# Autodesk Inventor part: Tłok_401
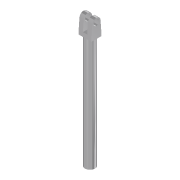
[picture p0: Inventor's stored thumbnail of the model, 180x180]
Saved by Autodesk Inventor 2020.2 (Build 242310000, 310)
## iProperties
Created: 2006-06
Part Number: Tłok_401
Document SubType Name: Modeling
Designer: F.Stasiak
Density: 1 g/cm^3
Material: Ogólny
Appearance: Chrom
Catalog Web Link: www.expertbooks.pl
Manager: www.cadconsulting.pl
Company: Fabian Stasiak CAD Consulting
Author: F.Stasiak
Subject: Zbiór ćwiczeń. Autodesk Inventor 2020. Kurs Professional
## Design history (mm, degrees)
sketch "Szkic1"
  geometry: C1 r 17.5 at (0, 0); 1 further point
  constraints: 1 centre point, 1 coincident
  dimensions: "d0" = 35 diameter of C1
extrude "Wyciągnięcie proste1" new body sketch "Szkic1" distance "d1" = 400; taper "d2" = 0 deg
sketch "Szkic2"
  geometry: L1 (-22.5, 17.5)-(22.5, 17.5); L2 (22.5, 17.5)-(22.5, -17.5); L3 (22.5, -17.5)-(-22.5, -17.5); L4 (-22.5, -17.5)-(-22.5, 17.5); L5 (0, 17.5)-(0, -17.5); C1 r 17.5 at (0, 0) reference; 1 further point
  constraints: 10 end point, 3 midpoint, 2 parallel, 2 tangent, 1 coincident, 1 horizontal, 1 perpendicular
  dimensions: "d3" = 45 distance of L2.end L3.end
extrude "Wyciągnięcie proste2" join sketch "Szkic2" distance "d4" = 15; taper "d5" = 0 deg
sketch "Szkic3"
  geometry: L1 (-15, 35)-(-15, 0) reference; L2 (-15, 35)-(-51.053, 32.463); L3 (-51.053, 2.537)-(-15, 0); L4 (-50, 17.5)-(-15, 17.5); C1 r 10 at (-50, 17.5); A1 r 15 centre (-50, 17.5) between (-51.053, 32.463) and (-51.053, 2.537)
  constraints: 6 end point, 2 centre point, 2 point on circle, 2 tangent, 1 coincident, 1 horizontal, 1 midpoint
  dimensions: "d6" = 15 radius of A1; "d7" = 35 distance of L4.start L4.end; "d8" = 20 diameter of C1
extrude "Wyciągnięcie proste3" join sketch "Szkic3" distance "d9" = 15; taper "d10" = 0 deg
node "Płaszczyzna konstrukcyjna1"
mirror "Lustro1"
node "Bryła1"
node "Korpusy bryłowe"
node "Korpusy powierzchniowe"
